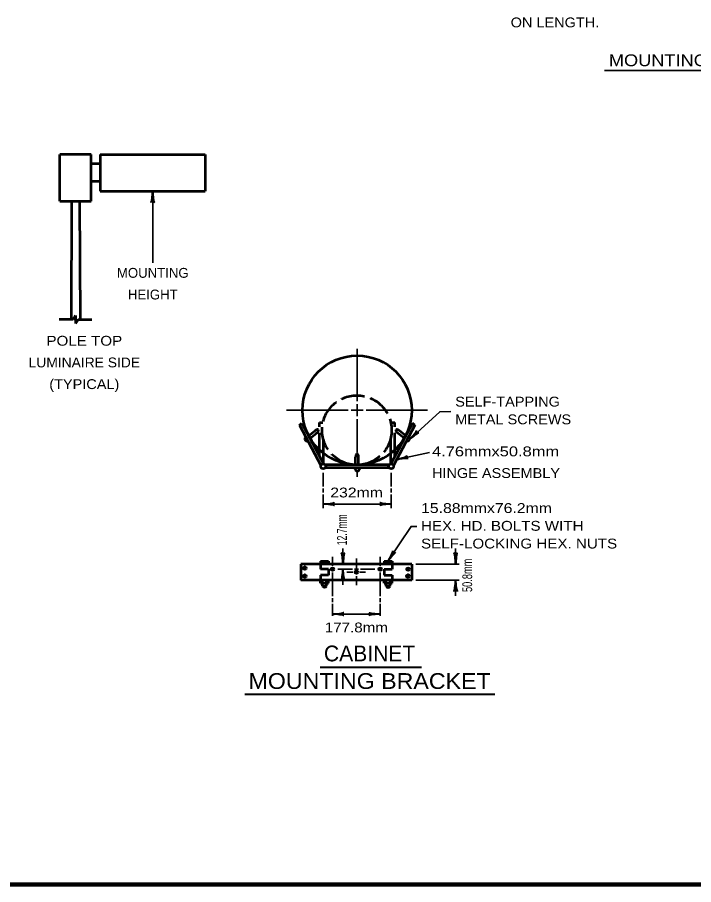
# Model space of a CAD drawing. Extents: x -20 to 693, y -19 to 435.
# Drawn here: x 170.8 to 342.4, y -9.1 to 211 of the extents above; entities that cross this region are included whole.
import ezdxf
from ezdxf.enums import TextEntityAlignment as Align

# ---------------------------------------------------------------- set-up
doc = ezdxf.new("R2010")
doc.units = 0
doc.linetypes.add('LONG_DASHED', pattern=[7.5, 6, -1.5])
doc.layers.add('1', color=7, linetype='Continuous', lineweight=53)

msp = doc.modelspace()

# ---------------------------------------------------------------- linework, layer by layer
at = {"layer": '1', "lineweight": 35}
for p, q in [((319.818, 197.514), (375.824, 197.514)), ((205.139, 148.708), (205.139, 166.875)), ((257.021, 126.928), (257.021, 113.568)), ((257.021, 112.808), (257.021, 109.788)), ((239.121, 111.308), (254.761, 111.308)), ((255.501, 111.308), (258.541, 111.308)), ((259.281, 111.308), (274.901, 111.308)), ((257.022, 109.028), (257.021, 100.588)), ((267.079, 98.822), (275.382, 100.546)), ((248.389, 95.441), (248.389, 91.941)), ((257.021, 95.668), (257.021, 94.408)), ((265.694, 95.441), (265.694, 91.941)), ((248.389, 91.441), (248.389, 90.441)), ((265.694, 91.441), (265.694, 90.441)), ((248.389, 89.941), (248.389, 86.441)), ((265.694, 89.941), (265.694, 86.441)), ((248.389, 87.513), (265.694, 87.513)), ((253.418, 72.248), (253.418, 76.248)), ((282.009, 72.248), (282.009, 76.248)), ((250.781, 74.088), (250.781, 71.868)), ((256.821, 73.648), (256.821, 71.248)), ((262.881, 74.088), (262.881, 71.868)), ((252.161, 70.988), (255.821, 70.988)), ((253.418, 70.988), (253.418, 66.979)), ((256.321, 70.988), (257.341, 70.988)), ((257.841, 70.988), (261.481, 70.988)), ((271.941, 72.248), (282.941, 72.248)), ((250.781, 70.108), (250.781, 64.151)), ((254.441, 70.248), (255.961, 70.248)), ((256.821, 69.228), (256.821, 66.888)), ((257.721, 70.248), (259.181, 70.248)), ((262.881, 70.108), (262.881, 64.151)), ((271.941, 68.228), (282.941, 68.228)), ((282.009, 64.228), (282.009, 68.228)), ((250.781, 63.651), (250.781, 62.651)), ((250.781, 62.151), (250.781, 59.148)), ((262.881, 63.651), (262.881, 62.651)), ((262.881, 62.151), (262.881, 59.148)), ((250.781, 59.592), (262.881, 59.592))]:
    msp.add_line(p, q, dxfattribs=at)
at = {"layer": '1'}
for p, q in [((181.598, 164.365), (181.598, 176.196)), ((189.561, 176.165), (181.598, 176.196)), ((191.811, 176.165), (191.811, 166.875)), ((191.811, 176.165), (218.467, 176.165)), ((218.467, 176.165), (218.467, 166.875)), ((189.561, 173.915), (191.811, 173.915)), ((189.561, 169.415), (191.811, 169.415)), ((191.811, 166.875), (218.467, 166.875)), ((181.598, 164.365), (189.561, 164.335)), ((184.56, 164.354), (184.44, 134.354)), ((186.599, 164.346), (186.718, 134.355)), ((184.94, 134.354), (181.44, 134.354)), ((184.94, 134.354), (185.578, 135.355)), ((185.578, 135.355), (185.58, 133.355)), ((186.218, 134.355), (185.58, 133.355)), ((186.218, 134.355), (189.718, 134.355)), ((242.361, 107.508), (243.001, 108.028)), ((243.001, 108.028), (248.501, 97.688)), ((271.061, 108.028), (265.561, 97.708)), ((271.701, 107.508), (271.061, 108.028)), ((242.361, 107.508), (247.821, 97.248)), ((271.701, 107.508), (266.241, 97.248)), ((265.121, 97.428), (248.941, 97.428)), ((265.141, 96.688), (248.901, 96.688)), ((247.761, 73.008), (247.761, 72.248)), ((247.761, 73.008), (249.781, 73.008)), ((248.261, 73.008), (248.261, 72.248)), ((249.261, 73.008), (249.261, 72.248)), ((249.781, 73.008), (249.781, 72.248)), ((263.881, 73.008), (263.882, 72.248)), ((263.881, 73.008), (265.901, 73.008)), ((264.381, 73.008), (264.381, 72.248)), ((265.401, 73.008), (265.401, 72.248)), ((265.901, 73.008), (265.901, 72.248)), ((270.941, 72.248), (242.721, 72.248)), ((242.721, 72.248), (242.721, 68.228)), ((247.761, 72.248), (247.761, 70.987)), ((249.781, 70.988), (247.761, 70.987)), ((249.781, 70.988), (249.781, 69.488)), ((263.881, 70.988), (263.881, 69.488)), ((263.881, 70.988), (265.901, 70.988)), ((265.901, 72.248), (265.901, 70.988)), ((270.941, 72.248), (270.941, 68.228)), ((270.941, 68.228), (242.721, 68.228)), ((249.781, 69.488), (247.761, 69.488)), ((247.761, 69.488), (247.761, 68.228)), ((263.881, 69.488), (265.901, 69.488)), ((265.901, 69.488), (265.901, 68.228)), ((247.761, 67.428), (247.761, 68.188)), ((247.761, 67.428), (249.781, 67.428)), ((248.261, 66.688), (248.261, 68.188)), ((248.261, 66.688), (249.261, 66.688)), ((249.261, 66.688), (249.261, 68.188)), ((249.781, 67.428), (249.781, 68.188)), ((263.881, 67.428), (263.881, 68.188)), ((263.881, 67.428), (265.901, 67.428)), ((264.381, 66.688), (264.381, 68.188)), ((264.381, 66.688), (265.401, 66.688)), ((265.401, 66.688), (265.401, 68.188)), ((265.901, 67.428), (265.901, 68.188))]:
    msp.add_line(p, q, dxfattribs=at)
at = {"layer": '1', "linetype": 'LONG_DASHED'}
for p, q in [((247.481, 99.588), (247.481, 108.168)), ((247.481, 108.168), (248.341, 108.168)), ((265.561, 108.168), (266.581, 108.168)), ((266.582, 99.588), (266.581, 108.168)), ((244.681, 104.848), (246.281, 106.088)), ((269.381, 104.848), (267.781, 106.088)), ((245.041, 104.168), (246.742, 105.508)), ((248.501, 97.688), (248.501, 103.768)), ((265.561, 97.708), (265.561, 104.348)), ((269.001, 104.168), (267.321, 105.508)), ((256.641, 97.428), (256.641, 99.408)), ((257.401, 97.428), (257.401, 99.408))]:
    msp.add_line(p, q, dxfattribs=at)
at = {"layer": '1', "lineweight": 40}
for p, q in [((247.673, 46.097), (273.383, 46.097)), ((228.502, 39.271), (291.984, 39.271))]:
    msp.add_line(p, q, dxfattribs=at)
at = {"layer": '1', "lineweight": 158}
msp.add_line((687.723, -9.063), (28.056, -9.063), dxfattribs=at)
at = {"layer": '1'}
msp.add_lwpolyline([(189.561, 164.335), (189.561, 169.415), (189.561, 176.165)], dxfattribs=at)
at = {"layer": '1', "lineweight": 35}
for points in [[(270.279, 103.918), (277.969, 110.922), (280.801, 110.971)], [(264.85, 73.008), (270.698, 81.847), (272.177, 81.847)]]:
    msp.add_lwpolyline(points, dxfattribs=at)
at = {"layer": '1'}
for centre, radius in [((257.021, 111.294), 13.86), ((248.418, 97.072), 0.63), ((265.627, 97.072), 0.63), ((243.724, 71.247), 0.378), ((250.775, 70.986), 0.378), ((256.836, 70.228), 0.378), ((262.871, 70.986), 0.378), ((269.942, 70.986), 0.378), ((243.724, 69.23), 0.378), ((269.917, 69.217), 0.378)]:
    msp.add_circle(centre, radius, dxfattribs=at)
at = {"layer": '1', "linetype": 'LONG_DASHED'}
msp.add_circle((256.956, 106.257), 8.82, dxfattribs=at)
at = {"layer": '1'}
for centre, radius, start, end in [((244.431, 104.123), 0.681, 138.1398, 277.864), ((269.641, 104.136), 0.681, 262.136, 41.8602), ((257.07, 96.546), 0.63, 167.65166, 11.75169), ((248.764, 66.972), 0.582, 209.9862, 330.0138), ((264.892, 66.936), 0.565, 206.79037, 333.20963)]:
    msp.add_arc(centre, radius, start, end, dxfattribs=at)
at = {"layer": '1', "lineweight": 40}
for centre, major_axis, ratio, start_param, end_param in [((204.927, 165.754), (0.176, 1.756), 0.07063, 3.1407148, 5.41811), ((204.927, 165.754), (0.176, 1.756), 0.07063, 3.1407148, 5.41811), ((205.415, 165.784), (-0.156, 1.786), 0.122415, 0.8963533, 3.1415927), ((205.415, 165.784), (-0.156, 1.786), 0.122415, 0.8963533, 3.1415927), ((270.9, 104.857), (-1.215, -1.318), 0.122415, 0.8963533, 3.1415927), ((270.9, 104.857), (-1.215, -1.318), 0.122415, 0.8963533, 3.1415927), ((271.25, 104.516), (1.417, 1.053), 0.07063, 6.2823074, 8.5597026), ((271.25, 104.516), (1.417, 1.053), 0.07063, 6.2823074, 8.5597026), ((268.091, 99.315), (-1.717, -0.516), 0.122415, 0.8963533, 3.1415927), ((268.219, 98.843), (1.755, 0.185), 0.07063, 6.2823074, 8.5597026), ((249.51, 87.301), (-1.756, 0.176), 0.07063, 3.1407148, 5.41811), ((249.51, 87.301), (-1.756, 0.176), 0.07063, 3.1407148, 5.41811), ((249.481, 87.789), (-1.786, -0.156), 0.122415, 0.8963533, 3.1415927), ((249.481, 87.789), (-1.786, -0.156), 0.122415, 0.8963533, 3.1415927), ((264.602, 87.237), (1.786, 0.156), 0.122415, 0.8963533, 3.1415927), ((264.573, 87.725), (1.756, -0.176), 0.07063, 3.1407148, 5.41811), ((253.142, 73.339), (0.156, -1.786), 0.122415, 0.8963533, 3.1415927), ((253.142, 73.339), (0.156, -1.786), 0.122415, 0.8963533, 3.1415927), ((253.63, 73.368), (-0.176, -1.756), 0.07063, 3.1407148, 5.41811), ((253.63, 73.368), (-0.176, -1.756), 0.07063, 3.1407148, 5.41811), ((265.221, 74.07), (-0.855, -1.575), 0.122415, 0.8963533, 3.1415927), ((265.221, 74.07), (-0.855, -1.575), 0.122415, 0.8963533, 3.1415927), ((265.644, 73.825), (1.116, 1.368), 0.07063, 6.2823074, 8.5597026), ((265.644, 73.825), (1.116, 1.368), 0.07063, 6.2823074, 8.5597026), ((281.732, 73.339), (0.156, -1.786), 0.122415, 0.8963533, 3.1415927), ((281.732, 73.339), (0.156, -1.786), 0.122415, 0.8963533, 3.1415927), ((282.22, 73.368), (-0.176, -1.756), 0.07063, 3.1407148, 5.41811), ((282.22, 73.368), (-0.176, -1.756), 0.07063, 3.1407148, 5.41811), ((253.207, 69.867), (0.176, 1.756), 0.07063, 3.1407148, 5.41811), ((253.207, 69.867), (0.176, 1.756), 0.07063, 3.1407148, 5.41811), ((253.694, 69.896), (-0.156, 1.786), 0.122415, 0.8963533, 3.1415927), ((253.694, 69.896), (-0.156, 1.786), 0.122415, 0.8963533, 3.1415927), ((281.797, 67.107), (0.176, 1.756), 0.07063, 3.1407148, 5.41811), ((282.285, 67.137), (-0.156, 1.786), 0.122415, 0.8963533, 3.1415927), ((251.902, 59.38), (-1.756, 0.176), 0.07063, 3.1407148, 5.41811), ((251.902, 59.38), (-1.756, 0.176), 0.07063, 3.1407148, 5.41811), ((251.873, 59.868), (-1.786, -0.156), 0.122415, 0.8963533, 3.1415927), ((251.873, 59.868), (-1.786, -0.156), 0.122415, 0.8963533, 3.1415927), ((261.79, 59.316), (1.786, 0.156), 0.122415, 0.8963533, 3.1415927), ((261.761, 59.804), (1.756, -0.176), 0.07063, 3.1407148, 5.41811)]:
    msp.add_ellipse(centre, major_axis=major_axis, ratio=ratio, start_param=start_param, end_param=end_param, dxfattribs=at)
at = {"layer": '1', "linetype": 'LONG_DASHED'}
for centre, major_axis, start_param, end_param in [((246.51, 105.798), (0.664, 0.518), 4.712389, 7.8539816), ((267.55, 105.798), (0.664, -0.518), 1.5707963, 4.712389), ((257.018, 99.416), (0.003, -0.842), 1.5707963, 4.712389)]:
    msp.add_ellipse(centre, major_axis=major_axis, ratio=0.448678, start_param=start_param, end_param=end_param, dxfattribs=at)

# ---------------------------------------------------------------- texts
at = {"layer": '1'}
for s, height, width, p in [('ON LENGTH.', 2.5, 1.1, (295.986, 208.456)), ('MOUNTING PLATE TYPE', 3, 1.15, (320.902, 198.598)), ('SELF-TAPPING', 2.5, 1.1, (281.916, 112.239)), ('METAL SCREWS', 2.5, 1.1, (281.916, 107.739)), ('4.76mmx50.8mm', 2.5, 1.25, (276.016, 99.615)), ('HINGE ASSEMBLY', 2.5, 1.1, (276.016, 94.115)), ('232mm', 2.5, 1.2, (250.189, 89.182)), ('15.88mmx76.2mm', 2.5, 1.2, (273.238, 85.231)), ('HEX. HD. BOLTS WITH', 2.5, 1.15, (273.238, 80.731)), ('SELF-LOCKING HEX. NUTS', 2.5, 1.15, (273.238, 76.231)), ('177.8mm', 2.5, 1.15, (248.811, 54.944))]:
    msp.add_text(s, height=height, dxfattribs=dict(at, width=width)).set_placement(p)
for s, height, p in [('MOUNTING', 2.5, (205.163, 144.915)), ('HEIGHT', 2.5, (205.163, 139.415)), ('CABINET', 4, (260.182, 47.597))]:
    msp.add_text(s, height=height, dxfattribs=at).set_placement(p, align=Align.CENTER)
for s, height, width, p in [('POLE TOP', 2.5, 1.15, (187.788, 127.68)), ('LUMINAIRE SIDE', 2.5, 1.05, (187.788, 122.18)), ('(TYPICAL)', 2.5, 1.1, (187.788, 116.68)), ('MOUNTING BRACKET', 4, 1.1, (260.182, 40.597))]:
    msp.add_text(s, height=height, dxfattribs=dict(at, width=width)).set_placement(p, align=Align.CENTER)
for s, width, p in [('12.7mm', 0.65, (254.421, 77.057)), ('50.8mm', 0.7, (286.21, 65.187))]:
    msp.add_text(s, height=2.5, rotation=90, dxfattribs=dict(at, width=width)).set_placement(p)

doc.saveas('drawing.dxf')
